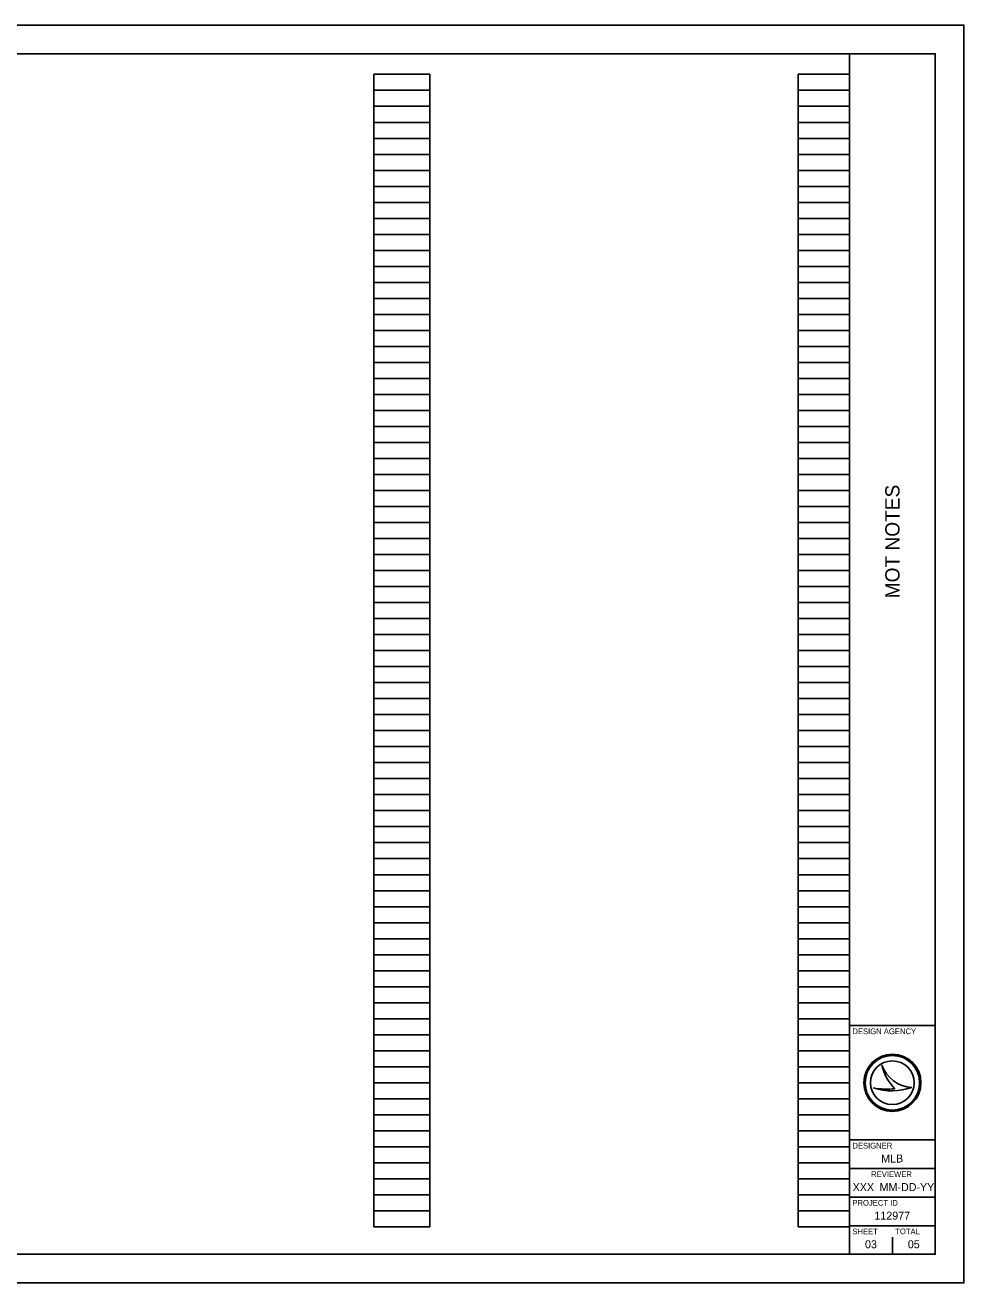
# Model space of a CAD drawing. Extents: x 0 to 34, y 0 to 22.
# Drawn here: x 17.58 to 34, y 0 to 22 of the extents above; entities that cross this region are included whole.
import ezdxf

# ---------------------------------------------------------------- set-up
doc = ezdxf.new("R2010")
doc.units = 0
for name, color, linetype in [('SH_Border', 7, 'Continuous'), ('SH_Cut_Line', 7, 'Continuous'), ('SH_Data', 7, 'Continuous')]:
    doc.layers.add(name, color=color, linetype=linetype)

msp = doc.modelspace()

# ---------------------------------------------------------------- linework, layer by layer
at = {"layer": 'SH_Border'}
for p, q in [((32, 0.5), (32, 21.5)), ((32, 4.5), (33.5, 4.5)), ((32, 2.5), (33.5, 2.5)), ((32, 2), (33.5, 2)), ((32, 1.5), (33.5, 1.5)), ((32, 1), (33.5, 1))]:
    msp.add_line(p, q, dxfattribs=at)
msp.add_lwpolyline([(1.5, 21.5), (33.5, 21.5), (33.5, 0.5), (1.5, 0.5)], close=True, dxfattribs=at)
at = {"layer": 'SH_Cut_Line'}
msp.add_lwpolyline([(0, 0), (34, 0), (34, 22), (0, 22)], close=True, dxfattribs=at)
at = {"layer": 'SH_Data'}
for p, q in [((23.68, 0.98), (23.68, 21.14)), ((23.68, 21.14), (24.66, 21.14)), ((24.66, 0.98), (24.66, 21.14)), ((31.1, 0.98), (31.1, 21.14)), ((31.1, 21.14), (32, 21.14)), ((32, 0.98), (32, 21.14)), ((23.68, 20.86), (24.66, 20.86)), ((31.1, 20.86), (32, 20.86)), ((23.68, 20.58), (24.66, 20.58)), ((31.1, 20.58), (32, 20.58)), ((23.68, 20.3), (24.66, 20.3)), ((31.1, 20.3), (32, 20.3)), ((23.68, 20.02), (24.66, 20.02)), ((31.1, 20.02), (32, 20.02)), ((23.68, 19.74), (24.66, 19.74)), ((31.1, 19.74), (32, 19.74)), ((23.68, 19.46), (24.66, 19.46)), ((31.1, 19.46), (32, 19.46)), ((23.68, 19.18), (24.66, 19.18)), ((31.1, 19.18), (32, 19.18)), ((23.68, 18.9), (24.66, 18.9)), ((31.1, 18.9), (32, 18.9)), ((23.68, 18.62), (24.66, 18.62)), ((31.1, 18.62), (32, 18.62)), ((23.68, 18.34), (24.66, 18.34)), ((31.1, 18.34), (32, 18.34)), ((23.68, 18.06), (24.66, 18.06)), ((31.1, 18.06), (32, 18.06)), ((23.68, 17.78), (24.66, 17.78)), ((31.1, 17.78), (32, 17.78)), ((23.68, 17.5), (24.66, 17.5)), ((31.1, 17.5), (32, 17.5)), ((23.68, 17.22), (24.66, 17.22)), ((31.1, 17.22), (32, 17.22)), ((23.68, 16.94), (24.66, 16.94)), ((31.1, 16.94), (32, 16.94)), ((23.68, 16.66), (24.66, 16.66)), ((31.1, 16.66), (32, 16.66)), ((23.68, 16.38), (24.66, 16.38)), ((31.1, 16.38), (32, 16.38)), ((23.68, 16.1), (24.66, 16.1)), ((31.1, 16.1), (32, 16.1)), ((23.68, 15.82), (24.66, 15.82)), ((31.1, 15.82), (32, 15.82)), ((23.68, 15.54), (24.66, 15.54)), ((31.1, 15.54), (32, 15.54)), ((23.68, 15.26), (24.66, 15.26)), ((31.1, 15.26), (32, 15.26)), ((23.68, 14.98), (24.66, 14.98)), ((31.1, 14.98), (32, 14.98)), ((23.68, 14.7), (24.66, 14.7)), ((31.1, 14.7), (32, 14.7)), ((23.68, 14.42), (24.66, 14.42)), ((31.1, 14.42), (32, 14.42)), ((23.68, 14.14), (24.66, 14.14)), ((31.1, 14.14), (32, 14.14)), ((23.68, 13.86), (24.66, 13.86)), ((31.1, 13.86), (32, 13.86)), ((23.68, 13.58), (24.66, 13.58)), ((31.1, 13.58), (32, 13.58)), ((23.68, 13.3), (24.66, 13.3)), ((31.1, 13.3), (32, 13.3)), ((23.68, 13.02), (24.66, 13.02)), ((31.1, 13.02), (32, 13.02)), ((23.68, 12.74), (24.66, 12.74)), ((31.1, 12.74), (32, 12.74)), ((23.68, 12.46), (24.66, 12.46)), ((31.1, 12.46), (32, 12.46)), ((23.68, 12.18), (24.66, 12.18)), ((31.1, 12.18), (32, 12.18)), ((23.68, 11.9), (24.66, 11.9)), ((31.1, 11.9), (32, 11.9)), ((23.68, 11.62), (24.66, 11.62)), ((31.1, 11.62), (32, 11.62)), ((23.68, 11.34), (24.66, 11.34)), ((31.1, 11.34), (32, 11.34)), ((23.68, 11.06), (24.66, 11.06)), ((31.1, 11.06), (32, 11.06)), ((23.68, 10.78), (24.66, 10.78)), ((31.1, 10.78), (32, 10.78)), ((23.68, 10.5), (24.66, 10.5)), ((31.1, 10.5), (32, 10.5)), ((23.68, 10.22), (24.66, 10.22)), ((31.1, 10.22), (32, 10.22)), ((23.68, 9.94), (24.66, 9.94)), ((31.1, 9.94), (32, 9.94)), ((23.68, 9.66), (24.66, 9.66)), ((31.1, 9.66), (32, 9.66)), ((23.68, 9.38), (24.66, 9.38)), ((31.1, 9.38), (32, 9.38)), ((23.68, 9.1), (24.66, 9.1)), ((31.1, 9.1), (32, 9.1)), ((23.68, 8.82), (24.66, 8.82)), ((31.1, 8.82), (32, 8.82)), ((23.68, 8.54), (24.66, 8.54)), ((31.1, 8.54), (32, 8.54)), ((23.68, 8.26), (24.66, 8.26)), ((31.1, 8.26), (32, 8.26)), ((23.68, 7.98), (24.66, 7.98)), ((31.1, 7.98), (32, 7.98)), ((23.68, 7.7), (24.66, 7.7)), ((31.1, 7.7), (32, 7.7)), ((23.68, 7.42), (24.66, 7.42)), ((31.1, 7.42), (32, 7.42)), ((23.68, 7.14), (24.66, 7.14)), ((31.1, 7.14), (32, 7.14)), ((23.68, 6.86), (24.66, 6.86)), ((31.1, 6.86), (32, 6.86)), ((23.68, 6.58), (24.66, 6.58)), ((31.1, 6.58), (32, 6.58)), ((23.68, 6.3), (24.66, 6.3)), ((31.1, 6.3), (32, 6.3)), ((23.68, 6.02), (24.66, 6.02)), ((31.1, 6.02), (32, 6.02)), ((23.68, 5.74), (24.66, 5.74)), ((31.1, 5.74), (32, 5.74)), ((23.68, 5.46), (24.66, 5.46)), ((31.1, 5.46), (32, 5.46)), ((23.68, 5.18), (24.66, 5.18)), ((31.1, 5.18), (32, 5.18)), ((23.68, 4.9), (24.66, 4.9)), ((31.1, 4.9), (32, 4.9)), ((23.68, 4.62), (24.66, 4.62)), ((31.1, 4.62), (32, 4.62)), ((23.68, 4.34), (24.66, 4.34)), ((31.1, 4.34), (32, 4.34)), ((23.68, 4.06), (24.66, 4.06)), ((31.1, 4.06), (32, 4.06)), ((23.68, 3.78), (24.66, 3.78)), ((31.1, 3.78), (32, 3.78)), ((32.567, 3.81), (32.567, 3.81)), ((23.68, 3.5), (24.66, 3.5)), ((31.1, 3.5), (32, 3.5)), ((32.417, 3.41), (32.417, 3.41)), ((32.75, 3.5), (32.75, 3.5)), ((33.087, 3.419), (33.087, 3.419)), ((23.68, 3.22), (24.66, 3.22)), ((31.1, 3.22), (32, 3.22)), ((23.68, 2.94), (24.66, 2.94)), ((31.1, 2.94), (32, 2.94)), ((23.68, 2.66), (24.66, 2.66)), ((31.1, 2.66), (32, 2.66)), ((23.68, 2.38), (24.66, 2.38)), ((31.1, 2.38), (32, 2.38)), ((23.68, 2.1), (24.66, 2.1)), ((31.1, 2.1), (32, 2.1)), ((23.68, 1.82), (24.66, 1.82)), ((31.1, 1.82), (32, 1.82)), ((23.68, 1.54), (24.66, 1.54)), ((31.1, 1.54), (32, 1.54)), ((23.68, 1.26), (24.66, 1.26)), ((31.1, 1.26), (32, 1.26)), ((23.68, 0.98), (24.66, 0.98)), ((31.1, 0.98), (32, 0.98)), ((32.375, 0.675), (32.375, 0.675)), ((32.75, 0.5), (32.75, 0.8))]:
    msp.add_line(p, q, dxfattribs=at)
for radius in [0.5, 0.477, 0.477, 0.382]:
    msp.add_circle((32.75, 3.5), radius, dxfattribs=at)
for centre, radius, start, end in [((33.116, 3.998), 0.58, 198.9257, 198.9319), ((33.347, 3.97), 0.796, 191.6379, 191.6421), ((33.116, 3.998), 0.58, 198.9319, 267.1657), ((33.347, 3.97), 0.796, 191.6421, 226.0947), ((32.739, 4.37), 1.013, 251.4576, 290.0832), ((32.648, 4.654), 1.266, 259.4964, 259.4995), ((32.739, 4.37), 1.013, 251.4527, 251.4576), ((32.648, 4.654), 1.266, 259.4995, 276.6672)]:
    msp.add_arc(centre, radius, start, end, dxfattribs=at)

# ---------------------------------------------------------------- texts
msp.add_text('MOT NOTES', height=0.25, rotation=90, dxfattribs=at).set_placement((32.875, 11.974))
for s, height, p in [('DESIGN AGENCY', 0.1, (32.05, 4.35)), ('DESIGNER', 0.1, (32.05, 2.35)), ('MLB', 0.14, (32.554, 2.105)), ('REVIEWER', 0.1, (32.378, 1.85)), ('XXX', 0.14, (32.055, 1.605)), ('MM-DD-YY', 0.14, (32.526, 1.605)), ('PROJECT ID', 0.1, (32.05, 1.35)), ('112977', 0.14, (32.435, 1.105)), ('SHEET', 0.1, (32.05, 0.85)), ('TOTAL', 0.1, (32.8, 0.85)), ('03', 0.14, (32.271, 0.605)), ('05', 0.14, (33.02, 0.605))]:
    msp.add_text(s, height=height, dxfattribs=at).set_placement(p)

doc.saveas('drawing.dxf')
